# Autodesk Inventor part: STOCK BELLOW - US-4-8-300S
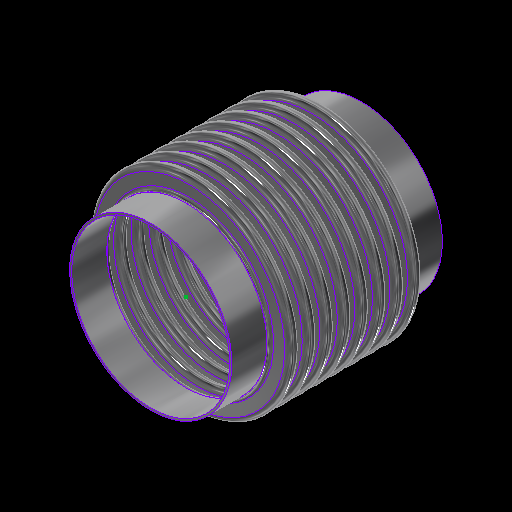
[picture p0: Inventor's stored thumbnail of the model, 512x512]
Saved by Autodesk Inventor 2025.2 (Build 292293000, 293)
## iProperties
Category: 22 GA (0.030 THICK)
RuleStatus: InUse
Created: 2024-01
Part Number: STOCK BELLOW - US-4-8-300S
Project: =STOCK BELLOWS: <Stock Number><SFILL>
Material: ASTM A240-304
Description: =STOCK BELLOWS: <Stock Number>, <SID_> I.D., <SOD_> O.D., <SPLY_> PLY, <Category>, <SNET_CONS> CONS.<PITCH_><STANGENT_> TANGENT<SFILL>
Document SubType Name: Sheet Metal
Designer: GS
Stock Number: U.S-4-8-300S
Surface Area: 2755.36 cm^2
Volume: 207.423 cm^3
Sheet Metal Rule: Default
Appearance: STAINLESS STEEL
Mass: 1671.27 g
Density: 8.05729 g/cm^3
THK: 0.036
ID: 3.500
OD: 4.250
CONS_: 2
PITCH: 0.500
TANGENT: 0.500
BELLOWS_UPSET: 0.000
d79: 1.000
d82: 1.000
d83: 26.000
d84: 24.000
d174: 8
d214: 8
STHK_: 0.030
SID_: 4.500
SOD_: 5.750
SPITCH_: 0.500
STANGENT__: 1.000
SBELLOWS_UPSET_: 0.000
SDIFF_TAN: 1.000
d252: 2
d275: 2
d287: 0.050
d289: 0.500
d290: 0.000
SOD_NECK: 4 5/8
PLY: 1
PSET: 4.178
PBAR: 1.035
COUNTER: 1.500
NET_TUBE: 3.071
CONS: 2
S_CONS: 0
NET_CONS: 2
ID_M: 88.90 mm
OD_M: 107.95 mm
THK_M: 0.91 mm
ID_U: 3.500 in
OD_U: 4.250 in
THK_U: 0.036 in
TANGENT2: 0.500
TAN_TO_TAN: 1.000 in
d80: 2.571
d81: 10
SID: 2.375
SCONS_: 8
SPITCH: 0.250
STANGENT_: 1.000
SBELLOWS_UPSET: 0.000
SNET_CONS: 8
SS_CONS: 0
SCONS: 8
d190: 8
d191: 1
d192: 1
d193: 8
d194: 0
SIZE: 4.00
PRESSURE: 300
d230: 8
STANGENT: 4.000
SPLY_: 2
d233: 8
d234: 0
d263: 2
d265: 1
d268: 2
d269: 0
d286: 2
d288: 1
d291: 2
d292: 0
SREROLL: 0.750
BLETP: 0.000 ul
PRES_Copy: 85
MATTABLE: 20 GA (0.036 THICK)
PART_NUMBER: U.S-4-8-300S
PITCH_: =, <SPITCH_> PITCH,
CFILL: .
SFILL: .
MESH: ,
COMP: 0.77
EXT: 0.39
LAT: 0.20
ANG: 573
ASR: 2573
LSR: 6336
ANSR: 147
PRES: 300
COMPM: 7.7
EXTM: 3.85
LATM: 2.00
ASRM: 450.609
PRESM: 20.684
LSRM: 1109.624
ANSRM: 25.744
TEMPMIN: 20
TEMPMAX: 800
TEMPMINM: -7
TEMPMAXM: 427
WEIGHTM: 1.671
WEIGHT: 3.685
Author: GS
Keywords: 20 GA (0.036 THICK)
Comments: =STOCK BELLOW - <STOCK NUMBER>
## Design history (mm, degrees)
sketch "Sketch2"
  geometry: L1 (0, -177.245)-(0, 562.856) reference; L2 (45.364, 0)-(44.45, 0); L3 (48.082, -2.718)-(50.343, -2.718); L4 (48.082, -3.632)-(50.343, -3.632); L5 (50.343, -9.982)-(48.082, -9.982); L6 (50.343, -9.068)-(48.082, -9.068); L7 (45.364, -12.7)-(44.45, -12.7); L8 (48.082, 0)-(48.082, -12.7); L9 (50.343, -6.35)-(53.975, -6.35); L10 (44.45, 0)-(44.45, -12.7); L11 (20.376, 102.841)-(20.376, 101.926); L12 (58.262, 457.127)-(58.262, 349.177); L13 (58.262, 444.427)-(58.262, 336.477); L14 (93.133, -58.817)-(93.133, -71.517); L15 (118.746, -66.401)-(118.746, -66.401); L16 (50.343, -9.068)-(50.343, -9.982); L17 (48.082, -9.068)-(48.082, -9.982); L18 (48.082, -9.525)-(50.343, -9.525); L19 (53.975, 0)-(53.975, -12.7); L20 (-50.343, -9.068)-(-50.343, -9.982); L21 (-50.343, -2.718)-(-48.082, -2.718); L22 (-50.343, -3.632)-(-48.082, -3.632); L23 (-48.082, -9.068)-(-50.343, -9.068); L24 (-50.343, -9.525)-(-48.082, -9.525); L25 (-48.082, -9.982)-(-50.343, -9.982); L26 (-48.082, -9.068)-(-48.082, -9.982); L27 (-44.45, 0.653)-(-44.45, -12.047); L28 (-48.082, -6.35)-(-44.45, -6.35); L29 (-50.343, 0.653)-(-50.343, -12.7); L30 (-53.061, 0)-(-53.975, 0); L31 (-53.975, 0)-(-53.975, -12.7); L32 (-53.061, -12.7)-(-53.975, -12.7); A1 r 2.718 centre (48.082, 0) between (45.364, 0) and (48.082, -2.718); A2 r 3.632 centre (48.082, 0) between (44.45, 0) and (48.082, -3.632); A3 r 3.632 centre (50.343, -6.35) between (50.343, -9.982) and (50.343, -2.718); A4 r 2.718 centre (50.343, -6.35) between (50.343, -9.068) and (50.343, -3.632); A5 r 2.718 centre (48.082, -12.7) between (48.082, -9.982) and (45.364, -12.7); A6 r 3.632 centre (48.082, -12.7) between (48.082, -9.068) and (44.45, -12.7); A7 r 3.175 centre (50.343, -6.35) between (50.343, -9.525) and (53.518, -6.35); A8 r 3.175 centre (48.082, -12.7) between (48.082, -9.525) and (44.907, -12.7); A9 r 2.718 centre (-50.343, -12.7) between (-50.343, -9.982) and (-53.061, -12.7); A10 r 2.718 centre (-48.082, -6.35) between (-48.082, -9.068) and (-48.082, -3.632); A11 r 3.175 centre (-48.082, -6.35) between (-48.082, -9.525) and (-44.907, -6.35); A12 r 3.632 centre (-48.082, -6.35) between (-48.082, -9.982) and (-48.082, -2.718); A13 r 3.175 centre (-50.343, -12.7) between (-50.343, -9.525) and (-53.518, -12.7); A14 r 3.632 centre (-50.343, -12.7) between (-50.343, -9.068) and (-53.975, -12.7); A15 r 2.718 centre (-50.343, 0) between (-53.061, 0) and (-50.343, -2.718); A16 r 3.632 centre (-50.343, 0) between (-53.975, 0) and (-50.343, -3.632); 10 further points
  constraints: 62 end point, 38 point on circle, 20 tangent, 16 centre point, 12 parallel, 9 midpoint, 7 vertical, 6 coincident, 6 concentric, 6 point on line, 4 equal radius, 4 perpendicular, 3 horizontal, 1 collinear, 1 horizontal alignment, 10 other
  dimensions: "THK" = 0.9144 distance of L11.start L11.end; "ID" = 88.9 distance of L11.end point (20.376, 13.026); "OD" = 107.95 distance of L12.start L12.end; "PITCH" = 12.7 distance of L12.start L13.start; "TANGENT" = 12.7 distance of L14.start L14.end; "BELLOWS_UPSET" = 0 distance of L15.start L15.end; "d43" = 88.9 diameter of L10 L1 (= ID); "d44" = 107.95 diameter of L9.end L1 (= OD); "d45" = 0.9144 distance between parallel lines of L5 L6 (computed from THK, PLY); "d46" = 3.6322 radius of A3 (computed from PITCH, THK, PLY); "UPSET_PITCH" = 12.7 distance of L2.end L7.end (derived); "SIDEWALL_ANGLE" = 360 deg dimension on L3 L9 (derived); "CON_GAP" = 5.4356 distance of point (48.082, -9.068) point (48.082, -3.632) (derived); "TAN1" = 4.98728 dimension on A8 (derived); "TAN2" = 4.98728 dimension on A7 (derived); "LEG1" = 2.2606 distance of L18.start L18.end (derived); "d278" = 0.9144 distance between parallel lines of L25 L23 (derived); "d279" = 3.6322 radius of A12 (derived); "d280" = 12.7 distance of L30.end L31.end (derived); "d281" = 360 deg dimension on L21 L28 (derived); "d282" = 5.4356 distance of point (-50.343, -9.068) point (-50.343, -3.632) (derived); "d283" = 4.98728 dimension on A13 (derived); "d284" = 4.98728 dimension on A11 (derived); "d285" = 2.2606 distance of L24.start L24.end (derived); "d293" = 88.9 diameter of L27 L1 (derived); "d294" = 107.95 diameter of L31 L1 (derived)
  node "Sketch Rectangular Pattern1" dims "d31" = 25.4, "ID" = 88.9
  node "Sketch Rectangular Pattern2" dims "d39" = 25.4, "PITCH" = 12.7
revolve "CONS" stored, may be unused: angle "d48" = 90 deg
node "BELLOW MIDPLANE"
pattern_linear "Rectangular Pattern2" dims "d52" = 12.7 (= UPSET_PITCH)
sketch "Sketch5"
  geometry: C1 r 45.364 at (0, 0) reference; C2 r 44.45 at (0, 0) reference
extrude "TANGENT" new body sketch "Sketch5" distance "d53" = 12.7 (= TANGENT); taper "d54" = 0 deg
revolve "SAMETAN" stored, may be unused: angle "d65" = 90 deg
revolve "DIFFTAN" stored, may be unused: angle "d70" = 90 deg
sketch "Sketch9"
  geometry: L1 (53.319, 0)-(-53.319, 0) reference; L2 (0, -17.78)-(0, 17.78) reference; L3 (38.085, 0)-(-38.085, 0); L4 (38.085, -11.906)-(38.085, 11.906); L5 (25.385, -11.906)-(25.385, 11.906); L6 (13.15, 11.906)-(13.15, -11.906); L7 (-25.385, -11.906)-(-25.385, 11.906); L8 (-38.085, -11.906)-(-38.085, 11.906); L9 (37.291, -11.906)-(37.291, 11.906); L10 (38.085, -11.906)-(37.291, -11.906); L11 (38.085, 11.906)-(37.291, 11.906); L12 (13.546, 11.906)-(12.753, 11.906); L13 (12.753, 11.906)-(12.753, -11.906); L14 (12.753, -11.906)-(13.546, -11.906); L15 (13.546, -11.906)-(13.546, 11.906); L16 (-13.546, 11.906)-(-13.546, -11.906); L17 (-13.15, 11.906)-(-13.15, -11.906); L18 (-13.546, -11.906)-(-12.753, -11.906); L19 (-12.753, -11.906)-(-12.753, 11.906); L20 (-12.753, 11.906)-(-13.546, 11.906); L21 (-38.085, -11.906)-(-37.291, -11.906); L22 (-37.291, -11.906)-(-37.291, 11.906); L23 (-37.291, 11.906)-(-38.085, 11.906); L24 (-38.085, 11.906)-(-38.085, -11.906); L25 (38.085, -0.397)-(-38.085, -0.397); L26 (-38.085, -0.397)-(-38.085, 0.397); L27 (-38.085, 0.397)-(38.085, 0.397); L28 (38.085, 0.397)-(38.085, -0.397); L29 (-38.085, 11.906)-(38.085, 11.906); L30 (38.085, 11.906)-(38.085, 12.7); L31 (38.085, 12.7)-(-38.085, 12.7); L32 (-38.085, 12.7)-(-38.085, 11.906); L33 (38.085, -11.906)-(-38.085, -11.906); L34 (-38.085, -11.906)-(-38.085, -12.7); L35 (-38.085, -12.7)-(38.085, -12.7); L36 (38.085, -12.7)-(38.085, -11.906); 30 further points
  constraints: 68 end point, 13 midpoint, 13 parallel, 8 horizontal, 7 perpendicular, 6 equal length, 3 point on line, 2 vertical, 14 other
  dimensions: "d115" = 23.8125 distance of L4.start L4.end (derived); "d116" = 12.7 distance between parallel lines of L4 L5 (derived); "d117" = 12.23516 distance between parallel lines of L5 L6 (derived); "d125" = 38.53427 distance between parallel lines of L7 L6 (derived); "d127" = 12.7 distance between parallel lines of L8 L7 (derived); "d128" = 24.93516 distance between parallel lines of L6 L4 (derived); "d130" = 76.16943 distance between parallel lines of L8 L4 (derived); "RULER_THK" = 0.79375 distance between parallel lines of L4 L9; "d135" = 0.79375 distance of L13.end L14.end (derived); "d138" = 26.29911 distance of L13.end L16.end (derived); "d143" = 0.79375 distance of L22.end L8.end (derived); "d144" = 0.79375 distance between parallel lines of L27 L25 (derived)
extrude "RULER" join sketch "Sketch9" distance "d149" = 0.79375 (derived); taper "d150" = 0 deg
extrude "BARS" join sketch "Sketch9" distance "d151" = 0.79375 (derived); taper "d152" = 0 deg
pattern_linear "Rectangular Pattern4" dims "d155" = 26.29911 (derived)
sketch "Sketch13"
  geometry: L1 (93.149, -52.467)-(93.149, -77.867); L2 (58.674, 0)-(57.15, 0); L3 (58.674, -12.7)-(57.15, -12.7); L4 (69.088, -10.287)-(61.087, -10.287); L5 (69.088, -8.763)-(61.087, -8.763); L6 (69.088, -6.35)-(73.025, -6.35); L7 (61.087, -2.413)-(69.088, -2.413); L8 (61.087, 0)-(61.087, -12.7); L9 (57.15, 0)-(57.15, -12.7); L10 (58.254, -350.381)-(58.254, -496.431); L11 (58.254, -363.081)-(58.254, -509.131); L12 (58.254, -388.481)-(58.254, -534.531); L13 (58.254, -401.181)-(58.254, -547.231); L14 (58.254, -413.881)-(58.254, -559.931); L15 (58.254, -426.581)-(58.254, -572.631); L16 (58.254, -439.281)-(58.254, -585.331); L17 (58.254, -375.781)-(58.254, -521.831); L18 (20.376, 102.688)-(20.376, 101.926); L19 (61.087, -3.937)-(69.088, -3.937); L20 (0, -722.935)-(0, 240.292) reference; L21 (-23.752, 0)-(142.514, 0) reference; A1 r 2.413 centre (61.087, 0) between (58.674, 0) and (61.087, -2.413); A2 r 2.413 centre (61.087, -12.7) between (61.087, -10.287) and (58.674, -12.7); A3 r 3.937 centre (61.087, -12.7) between (61.087, -8.763) and (57.15, -12.7); A4 r 2.413 centre (69.088, -6.35) between (69.088, -8.763) and (69.088, -3.937); A5 r 3.937 centre (69.088, -6.35) between (69.088, -10.287) and (69.088, -2.413); A6 r 3.937 centre (61.087, 0) between (57.15, 0) and (61.087, -3.937); 6 further points; 1 other entity
  constraints: 38 end point, 15 point on circle, 9 tangent, 6 centre point, 6 parallel, 5 vertical alignment, 4 point on line, 4 vertical, 3 coincident, 3 concentric, 2 collinear, 2 equal radius, 1 horizontal, 1 perpendicular, 23 other
  dimensions: "SBELLOWS_UPSET_" = 0 distance of point (118.762, -66.401) point (118.762, -66.401); "STOTAL_THK_BELLOW__" = 1.524 distance between parallel lines of L4 L5 (derived); "d224" = 3.937 radius of A5 (derived); "d225" = 12.7 distance of L2.end L3.end (derived); "SSIDEWALL_ANGLE_" = 360 deg dimension on L7 L6 (derived); "SSCON_GAP_" = 4.826 distance of point (61.087, -8.763) point (61.087, -3.937) (derived); "d235" = 114.3 diameter of L9 L20 (derived); "d236" = 146.05 diameter of L6.end L20 (derived)
  node "Sketch Rectangular Pattern4" dims "d228" = 25.4
  node "Sketch Rectangular Pattern5" dims "d229" = 25.4
revolve "SBELLOW" stored, may be unused: angle "d197" = 90 deg
pattern_linear "Rectangular Pattern5" dims "d204" = 12.7 (derived)
revolve "STANGENT" stored, may be unused: angle "d240" = 90 deg
revolve "SSAMETAN" stored, may be unused: angle "d241" = 90 deg
revolve "SDIFFTAN" stored, may be unused: angle "d246" = 90 deg
revolve "INVCON" stored, may be unused: angle "d295" = 90 deg
pattern_linear "Rectangular Pattern6" dims "d298" = 12.7 (derived)
revolve "INVTANGENT" stored, may be unused: angle "d302" = 90 deg
revolve "INVSAMETAN" stored, may be unused: angle "d307" = 90 deg
revolve "INVDIFFTAN" stored, may be unused: angle "d312" = 90 deg
sketch "ID BELLOW MOUNT CALC"
  geometry: L1 (44.45, 0)-(38.1, 0); L2 (38.1, 0)-(38.1, 12.7); L3 (38.1, 12.7)-(44.45, 12.7); L4 (44.45, 12.7)-(44.45, 0); L5 (36.513, 12.7)-(35.598, 12.7); L6 (35.598, 12.7)-(35.598, 0); L7 (35.598, 0)-(36.513, 0); L8 (36.513, 0)-(36.513, 12.7); L9 (0, -2.54)-(0, 15.24) reference; L10 (-8.89, 0)-(53.34, 0) reference; 1 further point
  constraints: 16 end point, 5 parallel, 2 collinear, 2 horizontal, 2 perpendicular
  dimensions: "d314" = 12.7 distance of L5.end L6.end (derived); "d315" = 0.9144 distance of L5.start L5.end (derived); "IG" = 1.5875 distance between parallel lines of L2 L8; "PIPE_OD" = 88.9 diameter of L4 L9; "PIPE_WALL" = 6.35 distance of L2.end L3.end; "ID_MT_BELLOW" = 71.1962 diameter of L6 L9 (derived)
revolve "CFILL" stored, may be unused: angle "d320" = 90 deg
pattern_linear "Rectangular Pattern7" dims "d323" = 12.7 (derived)
revolve "SFILL" stored, may be unused: angle "d324" = 90 deg
pattern_linear "Rectangular Pattern8" dims "d327" = 12.7 (derived)
node "STOCK BELLOW MIDPLANE"
node "BELLOW"
sketch "Sketch6"
  geometry: L1 (-12.7, 45.364)-(0, 45.364); L2 (0, 45.364)-(0, 44.45); L3 (0, 44.45)-(-12.7, 44.45); L4 (-12.7, 44.45)-(-12.7, 45.364); L5 (10.16, 0)-(-60.96, 0) reference; L6 (-38.1, -89.422)-(-38.1, 153.44) reference; 1 further point
  constraints: 8 end point, 2 parallel, 1 horizontal, 1 perpendicular
  dimensions: "d61" = 12.7 distance of L2.end L3.end (derived); "d62" = 0.9144 distance of L1.end L2.end (derived); "d63" = 88.9 diameter of L3 L5 (derived); "d64" = 25.4 distance between parallel lines of L4 L6 (derived)
sketch "Sketch12"
  geometry: 1 further point
sketch "Sketch14"
  geometry: L1 (-25.4, 58.674)-(0, 58.674); L2 (0, 58.674)-(0, 57.15); L3 (0, 57.15)-(-25.4, 57.15); L4 (-25.4, 57.15)-(-25.4, 58.674); L5 (5.08, 0)-(-30.48, 0) reference; L6 (0, -11.735)-(0, 70.409) reference; 1 further point
  constraints: 8 end point, 2 parallel, 1 collinear, 1 horizontal, 1 perpendicular
  dimensions: "d237" = 1.524 distance of L3.end L1.start (derived); "d238" = 114.3 diameter of L3 L5 (derived); "d239" = 25.4 distance of L1.start L1.end (derived); "SOD_NECK" = 117.348 diameter of L1 L5 (derived)
sketch "Sketch15"
  geometry: L1 (-11.735, 0)-(70.409, 0) reference; L2 (57.15, -101.6)-(58.674, -101.6); L3 (58.674, -101.6)-(58.674, -127); L4 (58.674, -127)-(57.15, -127); L5 (57.15, -127)-(57.15, -101.6); L6 (0, -154.94)-(0, 40.64) reference; 1 further point
  constraints: 8 end point, 2 parallel, 1 horizontal, 1 perpendicular
  dimensions: "d205" = 25.4 distance of L4.end L2.start (derived); "d206" = 1.524 distance of L3.end L4.end (derived); "d207" = 114.3 diameter of L5 L6 (derived); "d208" = 101.6 distance between parallel lines of L1 L2 (derived)
node "TANGENT_"
node "SAME_TAN"
sketch "Sketch8"
  geometry: L1 (45.364, -25.4)-(44.45, -25.4); L2 (44.45, -25.4)-(44.45, -38.1); L3 (44.45, -38.1)-(45.364, -38.1); L4 (45.364, -38.1)-(45.364, -25.4); L5 (0, -48.26)-(0, 22.86) reference; L6 (-89.422, 0)-(153.44, 0) reference; 1 further point
  constraints: 8 end point, 2 parallel, 1 horizontal, 1 perpendicular
  dimensions: "d66" = 88.9 diameter of L2 L5 (derived); "TOTAL_THK_BELLOW" = 0.9144 distance of L2.end L3.end (derived); "d68" = 25.4 distance between parallel lines of L1 L6 (derived); "d69" = 12.7 distance of L1.end L2.end (derived)
node "DIFF_TAN"
node "Sketch Rectangular Pattern3" dims "d138" = 26.29911 (derived), "d141" = 25.4
node "SBELLOW_"
node "STANGENT_"
node "SSAME_TAN"
sketch "Sketch16"
  geometry: L1 (58.674, -101.6)-(57.15, -101.6); L2 (57.15, -101.6)-(57.15, -127); L3 (57.15, -127)-(58.674, -127); L4 (58.674, -127)-(58.674, -101.6); L5 (0, -154.94)-(0, 40.64) reference; L6 (-11.735, 0)-(70.409, 0) reference; 1 further point
  constraints: 8 end point, 2 parallel, 1 horizontal, 1 perpendicular
  dimensions: "SDIFF_TAN" = 25.4 distance of L3.end L1.start; "d243" = 1.524 distance of L2.end L3.end (derived); "d244" = 101.6 distance between parallel lines of L1 L6 (derived); "d245" = 114.3 diameter of L2 L5 (derived)
node "SDIFF_TAN"
body "Solid15"
sketch "Sketch17"
  geometry: L1 (53.975, 12.7)-(53.061, 12.7); L2 (53.061, 12.7)-(53.061, 0); L3 (53.061, 0)-(53.975, 0); L4 (53.975, 0)-(53.975, 12.7); L5 (0, -2.54)-(0, 15.24) reference; L6 (-10.795, 0)-(64.77, 0) reference; 2 further points
  constraints: 8 end point, 2 parallel, 1 horizontal, 1 midpoint, 1 perpendicular, 1 point on line
  dimensions: "INVTANGENT" = 12.7 distance of L3.end L1.start (derived); "d300" = 0.9144 distance of L1.start L1.end (derived); "d301" = 107.95 diameter of L4 L5 (derived)
body "Solid16"
sketch "Sketch18"
  geometry: L1 (53.975, -25.4)-(53.061, -25.4); L2 (53.061, -25.4)-(53.061, -38.1); L3 (53.061, -38.1)-(53.975, -38.1); L4 (53.975, -38.1)-(53.975, -25.4); L5 (-10.795, 0)-(64.77, 0) reference; L6 (0, -48.26)-(0, 22.86) reference; 1 further point
  constraints: 8 end point, 2 parallel, 1 horizontal, 1 perpendicular
  dimensions: "d303" = 25.4 distance between parallel lines of L1 L5 (derived); "d304" = 12.7 distance of L3.end L1.start (derived); "d305" = 0.9144 distance of L2.end L3.end (derived); "d306" = 107.95 diameter of L4 L6 (derived)
body "Solid17"
sketch "Sketch19"
  geometry: L1 (53.975, -25.4)-(53.061, -25.4); L2 (53.061, -25.4)-(53.061, -38.1); L3 (53.061, -38.1)-(53.975, -38.1); L4 (53.975, -38.1)-(53.975, -25.4); L5 (0, -48.26)-(0, 22.86) reference; L6 (-10.795, 0)-(64.77, 0) reference; 1 further point
  constraints: 8 end point, 2 parallel, 1 horizontal, 1 perpendicular
  dimensions: "d308" = 12.7 distance of L1.end L2.end (derived); "d309" = 107.95 diameter of L4 L5 (derived); "d310" = 0.9144 distance of L2.end L3.end (derived); "d311" = 25.4 distance between parallel lines of L1 L6 (derived)
body "Solid18"
body "Solid19"
body "Solid20"
other parameters: "BMPL" = -50.8, "PSET" = 106.1212 (computed from OD, THK, PLY) [user parameter], "PBAR" = 26.29911 (= 0.570796 x PITCH + OD - ID) [user parameter; used in 1 equation term], "COUNTER" = 15 [user parameter], "NET_TUBE" = 77.99823 (computed from CONS_, PBAR, TANGENT) [user parameter], "S_CONS" = 0 [user parameter; used in 1 equation term], "ID_M" = 88.9 (= ID) [user parameter], "OD_M" = 107.95 (= OD) [user parameter], "THK_M" = 0.9144 (= THK) [user parameter], "ID_U" = 88.9 (= ID) [user parameter], "OD_U" = 107.95 (= OD) [user parameter], "THK_U" = 0.9144 (= THK) [user parameter], "D_UNITS" = 0 [user parameter], "TANGENT2" = 12.7 [user parameter], "TAN_TO_TAN" = 25.4 [user parameter], "OD_NECK" = 90.7288 [user parameter], "d79" = 25.4, "d80" = 65.29823 [user parameter], "d82" = 25.4, "d83" = 660.4, "d84" = 609.6, "sa_0" = 4, "FRAME_THK" = 0.79375 [user parameter], "CON_FLAT" = 12.23516 [user parameter], "SID" = 60.325 [user parameter], "SPITCH" = 6.35 [user parameter], "STANGENT_" = 25.4 [user parameter], "SBELLOWS_UPSET" = 0 [user parameter], "SS_CONS" = 0 [user parameter], "STAN_TO_TAN_" = 101.6 [user parameter], "d100" = 1.524 [user parameter], "d191" = 25.4 [user parameter], "d194" = 0 [user parameter], "STANGENT" = 101.6 [user parameter], "d234" = 0 [user parameter], "SUPSET_PITCH_" = 12.7 [user parameter], "d269" = 0 [user parameter], "d287" = 1.27, "d289" = 12.7, "d290" = 0, "d292" = 0 [user parameter], "Thickness" = 3.048 (derived), "KFactor" = 4.4, "BendRadius" = 3.048 (derived), "BendReliefWidth" = 3.048 (derived), "BendReliefDepth" = 1.524 (derived), "CornerReliefSize" = 12.192 (derived), "SeamGap" = 0.00508, "MinimumRemnant" = 6.096 (derived), "TransitionRadius" = 3.048 (derived), "JacobiRadiusSize" = 3.048 (derived), "GapSize" = 3.048 (derived), "SREROLL" = 19.05 [user parameter], "CUR_STK_PITCH" = 12.7 [user parameter], "d328" = -50.8 (derived), "ASR" = 25730 [user parameter], "LSR" = 63360 [user parameter], "BLETP" = 0 [user parameter], "ASRM" = 4506.0949 [user parameter], "PRESM" = 206.83949 [user parameter], "LSRM" = 11096.2368 [user parameter], "ANSRM" = 257.4411 [user parameter], "TEMPMIN" = 2664.83333 [user parameter], "TEMPMAX" = 6998.16667 [user parameter], "TEMPMINM" = 2664.83333 [user parameter], "TEMPMAXM" = 6998.16667 [user parameter], "WEIGHT" = 16.71266 [user parameter], "WEIGHTM" = 0.01671 [user parameter]
